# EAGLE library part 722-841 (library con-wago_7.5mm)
Serie 722, Federleiste mit abgewinkelten Einlötstiften / Series 722, Female connector with angled solder pins Polzahl / Pole No.: 11 Rastermaß / Pitch: 7.5 mm Bemessungsspannung / Rated Voltage: 630 V Nennstrom / Nominal Current: 12 A Lötstiftlänge: / Solder Pin Length: 5 mm Farbe / Color: lichtgrau / light gray Stand: 01.01.2012. Die jeweils aktuellen Daten zu diesem Artikel finden Sie in unserem Produktkatalog, den Sie unter www.wago.com einsehen können. As of: 01/01/2012. Please find the newest data for this article in our product catalogue, which can be viewed under www.wago.com.
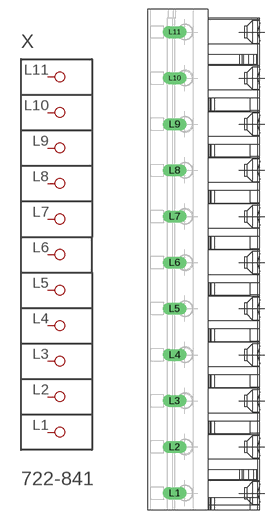
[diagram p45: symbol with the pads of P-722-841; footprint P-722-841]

Designator prefix X

## 722-841  [P-722-841]
L1  P1
L2  P2
L3  P3
L4  P4
L5  P5
L6  P6
L7  P7
L8  P8
L9  P9
L10  P10
L11  P11

## Footprint P-722-841 (pad centres in mm)
drill 1.3 long: L1 -5.15,-37.95; L2 -5.15,-30.45; L3 -5.15,-22.95; L4 -5.15,-15.45; L5 -5.15,-7.95; L6 -5.15,-0.45; L7 -5.15,7.05; L8 -5.15,14.55; L9 -5.15,22.05; L10 -5.15,29.55; L11 -5.15,37.05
